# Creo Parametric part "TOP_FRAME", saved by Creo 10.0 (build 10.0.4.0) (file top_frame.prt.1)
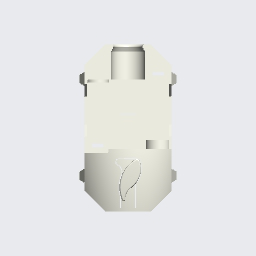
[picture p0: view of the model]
Units: millimeter Kilogram Sec (mmKs); MM, KILOGRAM, SECS

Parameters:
  SCREW_SIZE = "M3x.5"
  METRIC = "YES"

Other parameters: PITCH, DRILL_POINT_ANGLE, DRILL_DEPTH, DRILL_DIAMETER, THREAD_DIAMETER, THREADS_PER_INCH, THREAD_DEPTH, THREAD_LENGTH

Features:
  1. datum plane "RIGHT"
  2. datum plane "TOP"
  3. datum plane "FRONT"
  4. coordinate system
  5. protrusion
  6. chamfer
  7. cut
  8. curve
  9. cut
  10. cut
  11. curve
  12. cut
  13. cut
  14. cut
  15. cut
  16. cut
  17. cut
  18. protrusion
  19. protrusion
  20. cut
  21. cut
  22. cut
  23. cut
  24. protrusion
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
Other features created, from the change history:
  extrusion "Extrude 25"
  extrusion "Extrude 26"
  extrusion "Extrude 27"
  extrusion "Extrude 28"
  extrusion "Extrude 29"
  extruded cut "Extrude 30"
  extruded cut "Extrude 31"
  mirror "Mirror 3" (2 times)
  cut
  extruded cut "Extrude 31 (2)" (2 times)
  extrusion "Extrude 29 (2)"
  extruded cut "Extrude 30 (2)"
  extruded cut "Extrude 32"
  extruded cut "Extrude 33"
  extrusion "Extrude 34"
  hole "Hole 1"
  extruded cut "Extrude 35"
  sketch "Sketch 4"
  extruded cut "Extrude 36"
  extrusion "Extrude 37"
  revolved cut "Revolve 4"
  round "Round 1"

Notes: M3x.5 | 6.000 |  DRILL (  | 2.500 | 7.500 | HOLES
